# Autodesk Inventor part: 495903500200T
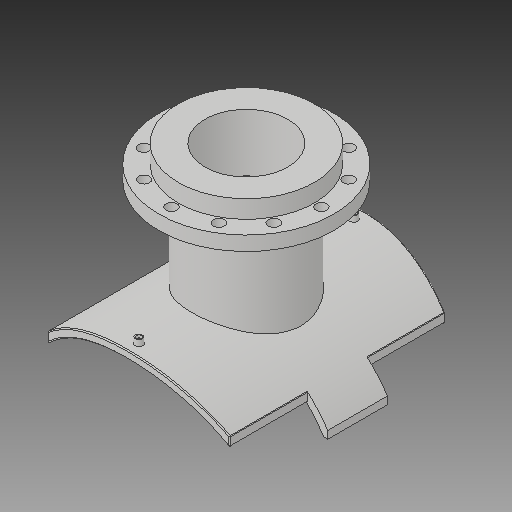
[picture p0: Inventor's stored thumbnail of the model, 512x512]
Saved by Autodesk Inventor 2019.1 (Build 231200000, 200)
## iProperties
Created: 2017-10
Part Number: 495903500200T
Material: Generic
Description: PLASSON FLANGED BRANCH SADDLE 500X200
Document SubType Name: Modeling
Designer: KIM
Mass: 2339.99 g
Surface Area: 3251.55 cm^2
Volume: 2339.99 cm^3
Density: 1 g/cm^3
Appearance: Default
Author: KIM
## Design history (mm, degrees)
derived "495904_495903.ipt"
feature "Solid1::495904_495903.ipt"
feature "Solid2::495904_495903.ipt"
tag "TaggingFeature1"
body "Solid1"
other parameters: "d1" = 15, "d2" = 358.2, "d4" = 0, "d6" = 117.5, "d7" = 0, "d12" = 275.6, "d13" = 14, "d14" = 211.5, "d16" = 5 deg, "d18" = 4, "d19" = 14, "d20" = 0, "d21" = 3, "d22" = 0, "d23" = 515, "d36" = 211.5, "d38" = 0, "d39" = 2, "d41" = 163, "d42" = 268, "d43" = 344, "d46" = 214.4, "d47" = 16, "d48" = 10.4, "d49" = 175, "d53" = 0, "d54" = 22, "d55" = 147.5, "d57" = 0, "d59" = 360 deg, "d61" = 28, "d63" = 0, "d67" = 15, "d68" = 125, "d70" = 0, "d71" = 2, "d72" = 398, "d_1" = 268, "B_" = 398, "x_" = 15, "D_" = 16, "DN_" = 163, "D_1" = 344, "t_" = 28, "s_" = 22, "Dp_" = 295
